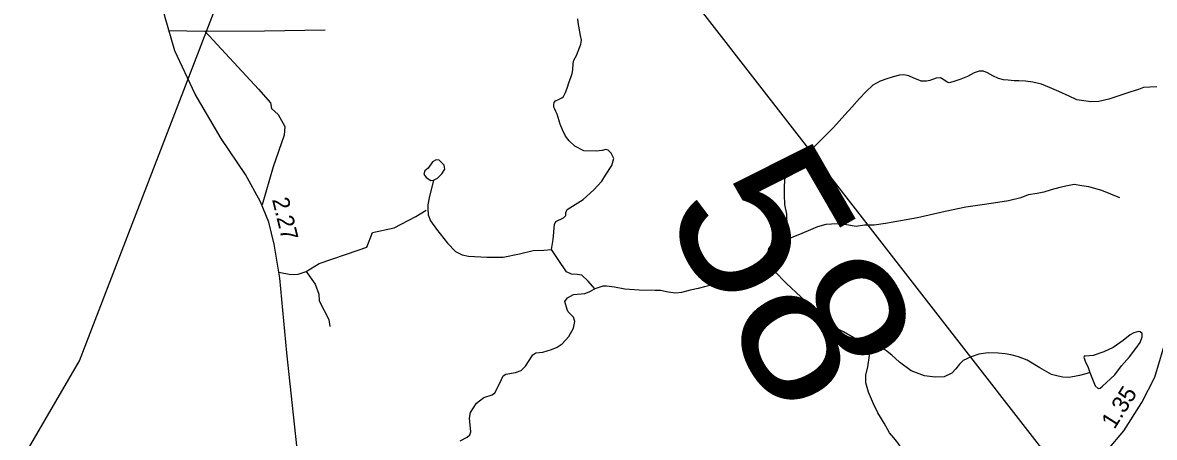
# Model space of a CAD drawing. Extents: x 2056842 to 2160602, y 826753 to 1016856.
# Drawn here: x 2087342 to 2095777, y 872106 to 875198 of the extents above; entities that cross this region are included whole.
import ezdxf

# ---------------------------------------------------------------- set-up
doc = ezdxf.new("R2010")
doc.units = 0
for name, color, linetype in [('Exist Hydrographic Creek Single Shore', 7, 'Continuous'), ('Exist Hydrographic Misc Water Feature', 7, 'Continuous'), ('Exist Road Non-System Type 51', 7, 'Continuous'), ('Exist Road Primary US Attributed', 7, 'Continuous'), ('Exist Road Primary US Mileage Hundredths English Label', 7, 'Continuous'), ('Exist Road Secondary Mileage Hundredths English Label', 7, 'Continuous'), ('Exist Road Secondary Structure Standard Bridge Number Label', 7, 'Continuous'), ('Exist Road Secondary Type 51 Attributed', 7, 'Continuous'), ('Exist Utilities Electrical Transmission Line', 7, 'Continuous'), ('Exist Utilities Telephone Line', 7, 'Continuous')]:
    doc.layers.add(name, color=color, linetype=linetype)

msp = doc.modelspace()

# ---------------------------------------------------------------- linework, layer by layer
at = {"layer": 'Exist Hydrographic Creek Single Shore'}
for points in [[(2091282.9, 873506.2), (2091296.7, 873580), (2091306.7, 873692), (2091316.7, 873714.5), (2091372.9, 873742), (2091390.4, 873759.5), (2091391.6, 873782), (2091401.6, 873805.8), (2091519.1, 873879.6), (2091600.3, 873950.8), (2091657.8, 874015.8), (2091685.2, 874062.1), (2091734, 874132.7), (2091747.7, 874184), (2091727.7, 874225.2), (2091705.2, 874247.7), (2091689, 874252.7), (2091660.3, 874244), (2091615.8, 874240.6), (2091525.3, 874241.5), (2091457.8, 874277.7), (2091416.6, 874316.5), (2091387.9, 874351.5), (2091365.4, 874398.1), (2091347.3, 874441.7), (2091325.2, 874515.7), (2091317.1, 874535.9), (2091308.9, 874551.8), (2091301, 874567.7), (2091300.7, 874587.7), (2091302.7, 874603.8), (2091314.8, 874615.7), (2091334.7, 874625.8), (2091360.8, 874638), (2091372.5, 874647.9), (2091388.6, 874678.1), (2091400.4, 874710), (2091416.5, 874757.9), (2091428.3, 874790.2), (2091438.1, 874818.2), (2091441.9, 874846), (2091445.9, 874894.1), (2091450, 874918), (2091469.7, 874952.1), (2091481.6, 874986.3), (2091495.4, 875018.1), (2091503.3, 875038.3), (2091507.5, 875066.4), (2091499.4, 875102.4), (2091483, 875198.2)], [(2091483, 875198.2), (2091479, 875226.2)], [(2095796.1, 874720.1), (2095743.8, 874717.8), (2095695.9, 874715.8), (2095657.9, 874699.6), (2095602.1, 874681.2), (2095526.3, 874657), (2095438.5, 874627), (2095362.2, 874610.5), (2095302.6, 874606.6), (2095250.7, 874614.5), (2095198.4, 874622.4), (2095142.2, 874650), (2095066.3, 874685.9), (2094996, 874713.5), (2094935.7, 874739.3), (2094872.2, 874755.1), (2094816.2, 874761), (2094768, 874764.7), (2094732.3, 874764.8), (2094688.2, 874768.3), (2094651.9, 874772.6), (2094616.3, 874782.4), (2094572, 874802.1), (2094533.8, 874824.2), (2094503.7, 874836.1), (2094472.1, 874836), (2094434, 874823.9), (2094383.7, 874797.8), (2094335.7, 874777.5), (2094275.9, 874757.3), (2094248.2, 874748.9), (2094232.2, 874755.1), (2094208, 874772.9), (2094184, 874787), (2094152, 874784.6), (2094104, 874766.7), (2094080, 874760.6), (2094040.1, 874760.6), (2094016.3, 874772.4), (2093984.1, 874784.1), (2093945.9, 874802), (2093909.9, 874809.9), (2093878.1, 874805.8), (2093830.3, 874793.6), (2093782.1, 874779.9), (2093732.3, 874761.4), (2093678.4, 874731.5), (2093626.5, 874683.3), (2093578.7, 874632.9), (2093522.5, 874568.8), (2093469, 874510.7), (2093385.3, 874416.3), (2093267.8, 874299.8), (2093216, 874244), (2093144, 874181.8), (2093084.1, 874125.5), (2093032.6, 874061.2), (2093020.5, 874029.4), (2093017.1, 873965.3), (2093018.9, 873917.2), (2093021, 873841.3), (2093035.5, 873769.4), (2093037.6, 873685.5), (2093029.8, 873633.5), (2093026.1, 873585.3)], [(2090404.5, 874022.6), (2090370.8, 873891.3), (2090360.8, 873840), (2090360.8, 873811.3), (2090364.5, 873766.3), (2090382, 873720), (2090425.8, 873657.3), (2090508.5, 873553.5), (2090568.7, 873491.6), (2090616.7, 873465.7), (2090664.7, 873458), (2090801.9, 873448.7), (2090924.3, 873448.7), (2091044.3, 873475), (2091148, 873498.7), (2091225.4, 873502.5), (2091282.9, 873506.2)], [(2095520.7, 873893), (2095384.8, 873946.9), (2095288.6, 873974.4), (2095236.3, 873982.4), (2095178.3, 873990.4), (2095128.5, 873982.1), (2095072.5, 873967.9), (2095008.5, 873951.6), (2094952.7, 873935.3), (2094904.8, 873925.1), (2094836.7, 873915.2), (2094783, 873892.8), (2094690.9, 873868.6), (2094578.9, 873852.3), (2094494.9, 873839.9), (2094371.2, 873821.4), (2094219.1, 873791.2), (2094011.4, 873742.4), (2093773.5, 873699.8), (2093689.8, 873687.7), (2093617.4, 873687.2), (2093553.7, 873679), (2093481.7, 873690.8), (2093421.8, 873698.6), (2093369.5, 873696.5), (2093329.4, 873692.4), (2093265.6, 873676.1), (2093213.7, 873653.9), (2093149.5, 873625.9), (2093070, 873593.7), (2093026.1, 873585.3)], [(2091607.8, 873213.9), (2091557.8, 873271.5), (2091508.7, 873314.6), (2091474.1, 873321.2), (2091431.6, 873323.7), (2091396.6, 873341.2), (2091334.1, 873432.5), (2091282.9, 873506.2)], [(2092818.4, 873392.9), (2092802.4, 873373), (2092786.8, 873352.6), (2092764.6, 873322.7), (2092748.6, 873310.5), (2092729, 873302.6), (2092676.9, 873290.6), (2092577, 873259.8), (2092505, 873248), (2092433.1, 873231.7), (2092377.1, 873215.4), (2092317.2, 873203), (2092253.4, 873187.1), (2092209.6, 873180.9), (2092153.4, 873188.9), (2092097.2, 873200.7), (2092057.2, 873200.3), (2091937.3, 873202.2), (2091829.2, 873209.7), (2091753.3, 873225.6), (2091693.4, 873233.1), (2091665.4, 873233.3), (2091607.8, 873213.9)], [(2093656, 872803.4), (2093624, 872813.4), (2093582.2, 872829.1), (2093536, 872849.1), (2093460.2, 872892.7), (2093373.8, 872938.6), (2093295.9, 873006.4), (2093223.5, 873080.3), (2093141.1, 873153.6), (2093034.9, 873253.4), (2092942.6, 873347.3), (2092883, 873379.1), (2092851, 873381), (2092818.4, 873392.9)], [(2090601.9, 872078.9), (2090654.4, 872107.4), (2090675.7, 872123.6), (2090683.2, 872146.1), (2090671.9, 872249.9), (2090679.4, 872292.4), (2090725.6, 872359.9), (2090779.4, 872402.4), (2090840.6, 872422.2), (2090861.8, 872437.2), (2090898.1, 872509.7), (2090924.3, 872563.5), (2090943.1, 872577.2), (2091015.5, 872588.5), (2091056.8, 872603.2), (2091089.2, 872635.7), (2091144.2, 872722), (2091166.7, 872735.7), (2091220.4, 872742), (2091282.9, 872762), (2091325.4, 872778.2), (2091362.9, 872803.3), (2091414.1, 872858.3), (2091447.8, 872920.8), (2091456.6, 872968.9), (2091447.8, 873002.7), (2091407.6, 873042.1), (2091399.7, 873058.3), (2091384.1, 873117.7), (2091402.9, 873145.2), (2091446.6, 873170.2), (2091531.6, 873177.7), (2091565.3, 873191.4), (2091607.8, 873213.9)], [(2095297, 872590.6), (2095266.5, 872578.7), (2095218.9, 872566.4), (2095182.8, 872558.5), (2095138.9, 872552.2), (2095094.9, 872554), (2095061, 872562), (2095011, 872575.7), (2094974.5, 872593.7), (2094922.6, 872623.5), (2094828.5, 872681.3), (2094764.5, 872705.2), (2094708.5, 872720.9), (2094664.2, 872728.8), (2094612.2, 872732.6), (2094538.5, 872736.1), (2094468.4, 872726.1), (2094412.2, 872705.8), (2094352.4, 872677.9), (2094324.1, 872652.3), (2094297.3, 872615.8), (2094266.9, 872584.2), (2094209.8, 872557.5), (2094144.2, 872553.8), (2094062.8, 872564.8), (2093965.5, 872602.5), (2093876.8, 872666.9), (2093820.9, 872718), (2093772.7, 872756), (2093656, 872803.4)]]:
    msp.add_lwpolyline(points, dxfattribs=at)
at = {"layer": 'Exist Hydrographic Misc Water Feature'}
for points in [[(2090404.5, 874022.6), (2090434.5, 874038.8), (2090467, 874071.3), (2090488.2, 874106.3), (2090484.5, 874135.1), (2090447, 874173.8), (2090424.5, 874176.3), (2090397, 874161.3), (2090364.5, 874112.6), (2090339.6, 874092.6), (2090333.3, 874068.8), (2090350.8, 874042.6), (2090384.5, 874021.3), (2090404.5, 874022.6)], [(2093026.1, 873585.3), (2093000, 873569.4), (2092972.2, 873555.4), (2092940.4, 873543.2), (2092914.1, 873528.8), (2092902.2, 873513.3), (2092894, 873477.2), (2092886.2, 873453.2), (2092876.8, 873418.9), (2092858.8, 873405), (2092818.4, 873392.9)], [(2095297, 872590.6), (2095325.4, 872514), (2095336.3, 872490.9), (2095359.4, 872470.3), (2095374, 872472.7), (2095391, 872488.5), (2095482.1, 872571.2), (2095532, 872638.1), (2095591.5, 872707.4), (2095640.2, 872769.4), (2095670.5, 872812), (2095686.3, 872855.8), (2095685.1, 872880.1), (2095671.8, 872892.3), (2095659.6, 872895.9), (2095624.3, 872886.2), (2095597.6, 872869.1), (2095545.3, 872827.8), (2095470, 872776.7), (2095399.5, 872743.9), (2095320.5, 872717.1), (2095265.8, 872712.3), (2095256.1, 872713.5), (2095252.4, 872703.8), (2095260.9, 872673.4), (2095282.8, 872627.1), (2095297, 872590.6)], [(2093972.6, 871722.3), (2093960.4, 871777.1), (2093931.2, 871886.4), (2093920.9, 871942.3), (2093908.8, 871982.2), (2093892.8, 872026.4), (2093864.7, 872066.1), (2093834.6, 872102.3), (2093802.6, 872140), (2093762.2, 872211.8), (2093715.9, 872287.9), (2093683.9, 872355.6), (2093647.4, 872443.5), (2093627.3, 872513.5), (2093627.3, 872569.5), (2093642.7, 872631.6), (2093652.7, 872715.4), (2093660.5, 872771.4), (2093656, 872803.4)]]:
    msp.add_lwpolyline(points, dxfattribs=at)
at = {"layer": 'Exist Road Non-System Type 51'}
msp.add_line((2088431.9, 875139.2), (2088699.9, 875134.7), dxfattribs=at)
for points in [[(2088699.9, 875134.7), (2089144.5, 875137), (2089595.8, 875145.6)], [(2088699.9, 875134.7), (2089098.9, 874701.2), (2089189.2, 874601.4), (2089196.8, 874557.6), (2089246.2, 874513.9), (2089295.6, 874422.6), (2089291.8, 874359.9), (2089208.2, 874122.2), (2089127.8, 873840.9)], [(2089454.3, 873342), (2089553.1, 873402.9), (2089841.9, 873501.7), (2089908.4, 873524.6), (2089950.2, 873632.9), (2090110.8, 873668.1), (2090272.3, 873753.7), (2090350.2, 873799.3)], [(2089250.9, 873336.5), (2089340.2, 873321.1), (2089395.4, 873323), (2089454.3, 873342)], [(2089454.3, 873342), (2089522.7, 873248.8), (2089549.3, 873172.8), (2089553.1, 873123.3), (2089625.3, 872984.5), (2089631, 872933.2)]]:
    msp.add_lwpolyline(points, dxfattribs=at)
at = {"layer": 'Exist Road Primary US Attributed'}
msp.add_lwpolyline([(2094179.6, 867992.5), (2094151.1, 868251.1), (2094156.8, 868467.8), (2094195.8, 868930.8), (2094230, 869299.7), (2094262.3, 869832.1), (2094306.9, 870380.7), (2094351.6, 870615.5), (2094459.9, 870896.9), (2094560.6, 871060.4), (2094700.2, 871257.2), (2095110.7, 871679.3), (2095427, 872011.1), (2095548.7, 872153.7), (2095683.6, 872366.7), (2095779.5, 872555.9), (2095872.6, 872862), (2095922, 873185.3), (2095961, 873452.4), (2095983.8, 873865), (2095966.7, 874108.4), (2095931.5, 874579)], dxfattribs=at)
at = {"layer": 'Exist Road Secondary Type 51 Attributed'}
msp.add_lwpolyline([(2089403.8, 871881.2), (2089310.7, 872736.1), (2089257.8, 873292.8), (2089217.6, 873546.2), (2089177.4, 873710.2), (2089115.6, 873863), (2089003.9, 874065.7), (2088822.1, 874334), (2088627.7, 874665.7), (2088475.8, 874989.2), (2088403.5, 875235.9), (2088339.5, 875501.2), (2088256.8, 876177.2), (2088159.2, 876823.4), (2088066.1, 877530.7), (2087947.7, 878394.6), (2087847.2, 879171.9), (2087812.9, 879416.4), (2087739.2, 879943.3), (2087696, 880266.8), (2087649, 880473.3), (2087577.5, 880646.2), (2087488.2, 880813.1), (2087343.7, 881023.3)], dxfattribs=at)
at = {"layer": 'Exist Utilities Electrical Transmission Line'}
msp.add_lwpolyline([(2090208.9, 878090.6), (2090399.6, 877911.2), (2091042.2, 877021.2), (2091166.6, 876875.7), (2095091.8, 871822.6), (2095202.4, 871658.9), (2098164.4, 867008.7), (2098184.9, 866904.8), (2098734, 864623.2), (2099022.7, 863475.6), (2099626.1, 861080), (2100400.4, 858056.5), (2100951.6, 855844.8), (2101980.8, 853661.7), (2102801.4, 851906.3), (2103296.8, 850944.6), (2103702.1, 850075), (2103840.6, 849731.1), (2105377.5, 846510.3), (2106244.1, 844636.9), (2107548.3, 841869.9), (2108761.2, 839864.8), (2109358.7, 838871.2), (2109834.3, 838086.5)], dxfattribs=at)
at = {"layer": 'Exist Utilities Telephone Line'}
msp.add_lwpolyline([(2070574.6, 855889.8), (2073540.2, 858741.1), (2079471.4, 864196.3), (2082575.1, 867047.6), (2086740, 870917.2), (2087764.9, 872677.4), (2089015.1, 875921.4), (2089705.6, 877143.4), (2092053.4, 881391.2), (2094430.2, 885697.2), (2096843.4, 888330.3), (2097766.5, 889363.1), (2100637.6, 891101.5), (2103123.5, 892599.9), (2104820.7, 893625.5), (2107244.8, 895109.3), (2108287.8, 895378.4), (2108625.8, 895633), (2109723.4, 896782.2), (2110232.2, 897204.1), (2110707.5, 898076.3)], dxfattribs=at)

# ---------------------------------------------------------------- texts
at = {"layer": 'Exist Road Primary US Mileage Hundredths English Label'}
msp.add_text('1.35', height=125, rotation=57.64583, dxfattribs=at).set_placement((2095479.1, 872160.8))
at = {"layer": 'Exist Road Secondary Mileage Hundredths English Label'}
msp.add_text('2.27', height=125, rotation=283.78207, dxfattribs=at).set_placement((2089200.1, 873880))
at = {"layer": 'Exist Road Secondary Structure Standard Bridge Number Label'}
msp.add_text('58', height=1230.31, rotation=300, dxfattribs=at).set_placement((2092094.8, 873797.3))

doc.saveas('drawing.dxf')
